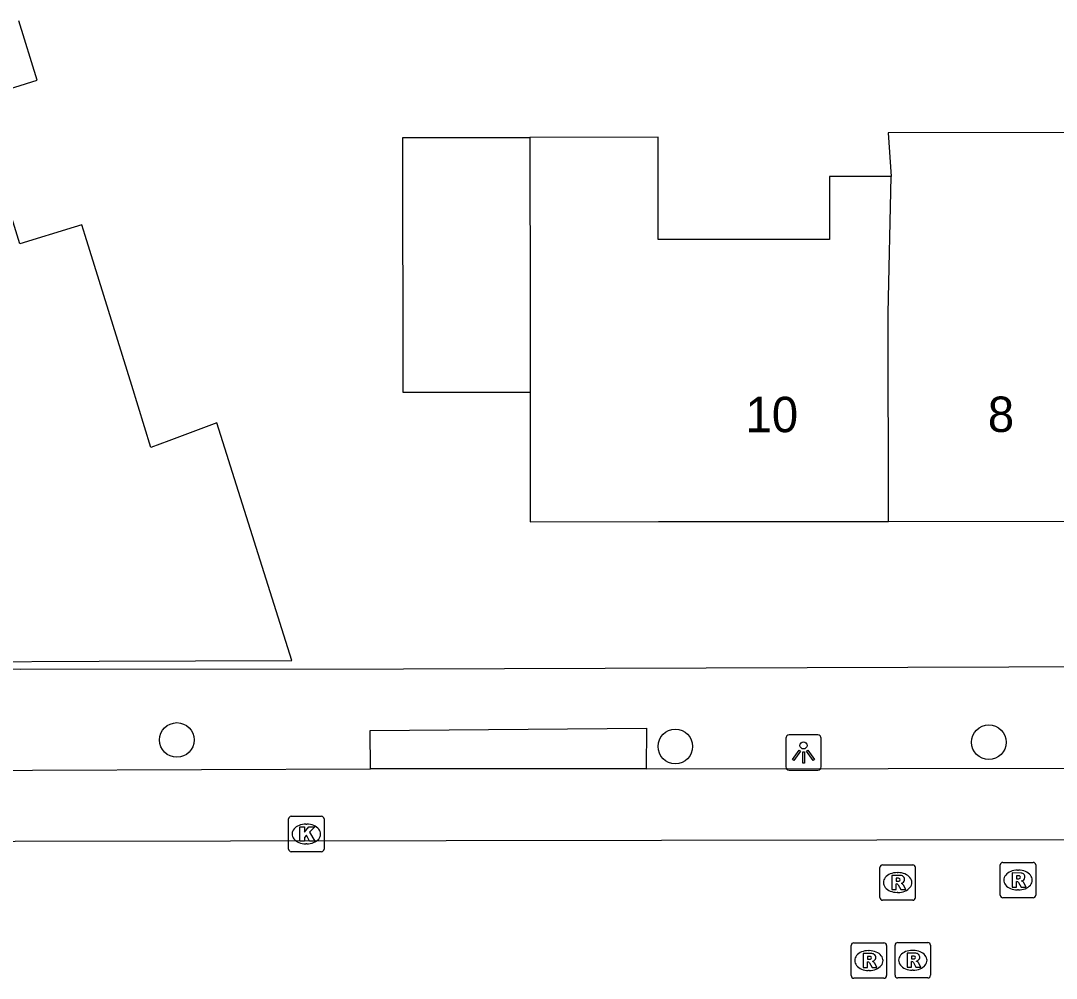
# Model space of a CAD drawing. Extents: x 160732 to 162105, y 387428 to 388479.
# Drawn here: x 161100.45 to 161129.69, y 388231.21 to 388258.26 of the extents above; entities that cross this region are included whole.
import ezdxf

# ---------------------------------------------------------------- set-up
doc = ezdxf.new("R2010")
doc.units = 0
for name, color, linetype in [('IMGEO_Boom', 7, 'Continuous'), ('IMGEO_Kolk', 7, 'Continuous'), ('IMGEO_Lichtpunt', 7, 'Continuous'), ('IMGEO_Muur', 7, 'Continuous'), ('IMGEO_Pand', 7, 'Continuous'), ('IMGEO_Pand_nummerreeks', 7, 'Continuous'), ('IMGEO_Rijbaan_lokaal_open', 7, 'Continuous'), ('IMGEO_Rioolput', 7, 'Continuous'), ('IMGEO_Voetpad_open', 7, 'Continuous')]:
    doc.layers.add(name, color=color, linetype=linetype)

msp = doc.modelspace()

# ---------------------------------------------------------------- linework, layer by layer
at = {"layer": 'IMGEO_Boom'}
for centre in [(161104.856, 388237.944), (161118.933, 388237.761), (161127.787, 388237.879)]:
    msp.add_circle(centre, 0.489, dxfattribs=at)
at = {"layer": 'IMGEO_Kolk'}
for p, q in [((161108.012, 388234.863), (161108.012, 388235.715)), ((161108.087, 388235.789), (161108.939, 388235.789)), ((161108.5, 388235.569), (161108.525, 388235.569)), ((161109.013, 388235.715), (161109.013, 388234.863)), ((161108.523, 388235.009), (161108.498, 388235.009)), ((161108.939, 388234.789), (161108.087, 388234.789))]:
    msp.add_line(p, q, dxfattribs=at)
for points in [[(161108.012, 388234.863), (161108.012, 388235.715)], [(161108.087, 388235.789), (161108.939, 388235.789)], [(161109.013, 388235.715), (161109.013, 388234.863)], [(161108.333, 388235.489), (161108.456, 388235.489), (161108.456, 388235.338), (161108.586, 388235.489), (161108.75, 388235.489), (161108.604, 388235.338), (161108.757, 388235.089), (161108.605, 388235.089), (161108.52, 388235.253), (161108.456, 388235.186), (161108.456, 388235.089), (161108.333, 388235.089), (161108.333, 388235.489)], [(161108.939, 388234.789), (161108.087, 388234.789)]]:
    msp.add_lwpolyline(points, dxfattribs=at)
for centre, start, end in [((161108.089, 388235.713), 91.552, 178.448), ((161108.089, 388235.713), 91.552, 178.448), ((161108.937, 388235.713), 1.552, 88.448), ((161108.937, 388235.713), 1.552, 88.448), ((161108.089, 388234.865), 181.552, 268.448), ((161108.089, 388234.865), 181.552, 268.448), ((161108.937, 388234.865), 271.552, 358.448), ((161108.937, 388234.865), 271.552, 358.448)]:
    msp.add_arc(centre, 0.0765, start, end, dxfattribs=at)
for centre, major_axis, ratio, start_param, end_param in [((161108.499, 388235.289), (-0.387, 0.002), 0.722429, 4.712389, 7.853982), ((161108.524, 388235.289), (-0.39, 0.002), 0.717154, 1.570796, 4.712389)]:
    msp.add_ellipse(centre, major_axis=major_axis, ratio=ratio, start_param=start_param, end_param=end_param, dxfattribs=at)
at = {"layer": 'IMGEO_Lichtpunt'}
for p, q in [((161122.054, 388237.991), (161122.054, 388237.184)), ((161122.054, 388237.991), (161122.054, 388237.184)), ((161122.956, 388238.086), (161122.148, 388238.086)), ((161122.956, 388238.086), (161122.148, 388238.086)), ((161123.05, 388237.184), (161123.05, 388237.991)), ((161123.05, 388237.184), (161123.05, 388237.991)), ((161122.148, 388237.09), (161122.956, 388237.09)), ((161122.148, 388237.09), (161122.956, 388237.09))]:
    msp.add_line(p, q, dxfattribs=at)
for points in [[(161122.428, 388237.655), (161122.467, 388237.627), (161122.279, 388237.365), (161122.241, 388237.392), (161122.428, 388237.655)], [(161122.53, 388237.607), (161122.577, 388237.607), (161122.577, 388237.285), (161122.53, 388237.285), (161122.53, 388237.607)], [(161122.64, 388237.627), (161122.678, 388237.654), (161122.865, 388237.392), (161122.826, 388237.364), (161122.64, 388237.627)]]:
    msp.add_lwpolyline(points, dxfattribs=at)
msp.add_circle((161122.553, 388237.789), 0.0994, dxfattribs=at)
for centre, start, end in [((161122.148, 388237.991), 90, 180), ((161122.148, 388237.991), 90, 180), ((161122.956, 388237.991), 0, 90), ((161122.956, 388237.991), 0, 90), ((161122.148, 388237.184), 180, 270), ((161122.148, 388237.184), 180, 270), ((161122.956, 388237.184), 270, 0), ((161122.956, 388237.184), 270, 360)]:
    msp.add_arc(centre, 0.0946, start, end, dxfattribs=at)
at = {"layer": 'IMGEO_Muur'}
msp.add_lwpolyline([(161111.252, 388239.945), (161100.452, 388239.931)], dxfattribs=at)
at = {"layer": 'IMGEO_Pand'}
for points in [[(161100.422, 388251.952), (161099.156, 388256.034), (161100.91, 388256.578), (161100.39, 388258.255)], [(161114.833, 388247.757), (161111.244, 388247.753), (161111.237, 388254.958), (161114.828, 388254.961)], [(161125.03, 388253.856), (161123.285, 388253.855), (161123.286, 388252.078), (161118.453, 388252.074), (161118.451, 388254.965), (161114.828, 388254.961)], [(161114.828, 388254.961), (161114.831, 388250), (161114.833, 388247.757)], [(161131.281, 388255.101), (161124.942, 388255.093), (161125.03, 388253.856)], [(161124.954, 388244.117), (161124.947, 388250), (161125.03, 388253.856)], [(161092.181, 388249.13), (161093.283, 388245.574), (161094.032, 388245.807), (161094.871, 388243.102), (161097.592, 388243.945), (161098.837, 388240.152), (161102.659, 388240.167), (161108.106, 388240.189), (161105.986, 388246.899), (161104.628, 388246.395), (161104.121, 388246.207), (161103.58, 388247.957), (161102.266, 388252.194), (161102.173, 388252.495), (161101.955, 388252.427), (161100.422, 388251.952)], [(161114.833, 388247.757), (161114.837, 388244.108), (161118.459, 388244.111), (161124.954, 388244.117)], [(161124.954, 388244.117), (161131.298, 388244.124)]]:
    msp.add_lwpolyline(points, dxfattribs=at)
at = {"layer": 'IMGEO_Rijbaan_lokaal_open'}
msp.add_lwpolyline([(161148.964, 388235.149), (161088.109, 388235.056)], dxfattribs=at)
at = {"layer": 'IMGEO_Rioolput'}
for p, q in [((161124.785, 388234.419), (161125.637, 388234.419)), ((161128.11, 388233.562), (161128.11, 388234.414)), ((161128.185, 388234.488), (161129.037, 388234.488)), ((161129.111, 388234.414), (161129.111, 388233.562)), ((161124.71, 388233.493), (161124.71, 388234.345)), ((161125.198, 388234.199), (161125.223, 388234.199)), ((161125.711, 388234.345), (161125.711, 388233.493)), ((161128.598, 388234.268), (161128.623, 388234.268)), ((161125.221, 388233.639), (161125.196, 388233.639)), ((161128.621, 388233.708), (161128.596, 388233.708)), ((161125.637, 388233.419), (161124.785, 388233.419)), ((161129.037, 388233.488), (161128.185, 388233.488)), ((161123.898, 388231.289), (161123.898, 388232.141)), ((161123.973, 388232.215), (161124.825, 388232.215)), ((161124.899, 388232.141), (161124.899, 388231.289)), ((161125.139, 388231.298), (161125.139, 388232.15)), ((161125.214, 388232.224), (161126.066, 388232.224)), ((161126.14, 388232.15), (161126.14, 388231.298)), ((161124.386, 388231.995), (161124.411, 388231.995)), ((161125.627, 388232.004), (161125.652, 388232.004)), ((161124.825, 388231.215), (161123.973, 388231.215)), ((161124.409, 388231.435), (161124.384, 388231.435)), ((161126.066, 388231.224), (161125.214, 388231.224)), ((161125.65, 388231.444), (161125.625, 388231.444))]:
    msp.add_line(p, q, dxfattribs=at)
for points in [[(161124.785, 388234.419), (161125.637, 388234.419)], [(161128.11, 388233.562), (161128.11, 388234.414)], [(161128.185, 388234.488), (161129.037, 388234.488)], [(161129.111, 388234.414), (161129.111, 388233.562)], [(161124.71, 388233.493), (161124.71, 388234.345)], [(161125.299, 388234.117), (161125.047, 388234.119), (161125.047, 388233.719)], [(161125.711, 388234.345), (161125.711, 388233.493)], [(161128.699, 388234.186), (161128.447, 388234.188), (161128.447, 388233.788)], [(161128.625, 388234.107), (161128.571, 388234.107), (161128.571, 388234.026)], [(161125.047, 388233.719), (161125.171, 388233.719), (161125.171, 388233.881), (161125.182, 388233.881)], [(161125.225, 388234.038), (161125.171, 388234.038), (161125.171, 388233.957)], [(161125.171, 388233.957), (161125.223, 388233.957)], [(161125.229, 388233.852), (161125.3, 388233.719), (161125.44, 388233.719), (161125.375, 388233.845)], [(161128.447, 388233.788), (161128.571, 388233.788), (161128.571, 388233.95), (161128.582, 388233.95)], [(161128.571, 388234.026), (161128.623, 388234.026)], [(161128.629, 388233.921), (161128.7, 388233.788), (161128.84, 388233.788), (161128.775, 388233.914)], [(161125.637, 388233.419), (161124.785, 388233.419)], [(161129.037, 388233.488), (161128.185, 388233.488)], [(161123.898, 388231.289), (161123.898, 388232.141)], [(161123.973, 388232.215), (161124.825, 388232.215)], [(161124.899, 388232.141), (161124.899, 388231.289)], [(161125.139, 388231.298), (161125.139, 388232.15)], [(161125.214, 388232.224), (161126.066, 388232.224)], [(161126.14, 388232.15), (161126.14, 388231.298)], [(161124.487, 388231.913), (161124.235, 388231.915), (161124.235, 388231.515)], [(161124.413, 388231.834), (161124.359, 388231.834), (161124.359, 388231.753)], [(161124.359, 388231.753), (161124.411, 388231.753)], [(161125.728, 388231.922), (161125.476, 388231.924), (161125.476, 388231.524)], [(161125.654, 388231.843), (161125.6, 388231.843), (161125.6, 388231.762)], [(161125.6, 388231.762), (161125.652, 388231.762)], [(161124.235, 388231.515), (161124.359, 388231.515), (161124.359, 388231.677), (161124.37, 388231.677)], [(161124.417, 388231.648), (161124.488, 388231.515), (161124.628, 388231.515), (161124.563, 388231.641)], [(161125.476, 388231.524), (161125.6, 388231.524), (161125.6, 388231.686), (161125.611, 388231.686)], [(161125.658, 388231.657), (161125.729, 388231.524), (161125.869, 388231.524), (161125.804, 388231.65)], [(161124.825, 388231.215), (161123.973, 388231.215)], [(161126.066, 388231.224), (161125.214, 388231.224)]]:
    msp.add_lwpolyline(points, dxfattribs=at)
for centre, radius, start, end in [((161124.787, 388234.343), 0.0765, 91.552, 178.448), ((161124.787, 388234.343), 0.0765, 91.552, 178.448), ((161125.635, 388234.343), 0.0765, 1.552, 88.448), ((161125.635, 388234.343), 0.0765, 1.552, 88.448), ((161128.187, 388234.412), 0.0765, 91.552, 178.448), ((161128.187, 388234.412), 0.0765, 91.552, 178.448), ((161129.035, 388234.412), 0.0765, 1.552, 88.448), ((161129.035, 388234.412), 0.0765, 1.552, 88.448), ((161125.298, 388234.007), 0.109, 350.3612, 89.416), ((161128.631, 388234.011), 0.0964, 77.0061, 93.1865), ((161128.645, 388234.068), 0.0378, 276.6634, 79.6772), ((161128.698, 388234.076), 0.109, 350.3612, 89.416), ((161125.181, 388233.828), 0.0533, 26.0293, 88.6989), ((161125.207, 388234.146), 0.19, 274.7715, 282.9687), ((161125.231, 388233.942), 0.0964, 77.0061, 93.1865), ((161125.245, 388233.999), 0.0378, 276.6634, 79.6772), ((161125.296, 388234.007), 0.112, 277.5842, 350.9817), ((161125.28, 388233.792), 0.108, 29.5134, 73.7905), ((161128.581, 388233.897), 0.0533, 26.0293, 88.6989), ((161128.607, 388234.215), 0.19, 274.7715, 282.9687), ((161128.696, 388234.076), 0.112, 277.5842, 350.9817), ((161128.68, 388233.861), 0.108, 29.5134, 73.7905), ((161128.187, 388233.564), 0.0765, 181.552, 268.448), ((161128.187, 388233.564), 0.0765, 181.552, 268.448), ((161129.035, 388233.564), 0.0765, 271.552, 358.448), ((161129.035, 388233.564), 0.0765, 271.552, 358.448), ((161124.787, 388233.495), 0.0765, 181.552, 268.448), ((161124.787, 388233.495), 0.0765, 181.552, 268.448), ((161125.635, 388233.495), 0.0765, 271.552, 358.448), ((161125.635, 388233.495), 0.0765, 271.552, 358.448), ((161123.975, 388232.139), 0.0765, 91.552, 178.448), ((161123.975, 388232.139), 0.0765, 91.552, 178.448), ((161124.823, 388232.139), 0.0765, 1.552, 88.448), ((161124.823, 388232.139), 0.0765, 1.552, 88.448), ((161125.216, 388232.148), 0.0765, 91.552, 178.448), ((161125.216, 388232.148), 0.0765, 91.552, 178.448), ((161126.064, 388232.148), 0.0765, 1.552, 88.448), ((161126.064, 388232.148), 0.0765, 1.552, 88.448), ((161124.395, 388231.942), 0.19, 274.7715, 282.9687), ((161124.419, 388231.738), 0.0964, 77.0061, 93.1865), ((161124.433, 388231.795), 0.0378, 276.6634, 79.6772), ((161124.486, 388231.803), 0.109, 350.3612, 89.416), ((161124.484, 388231.803), 0.112, 277.5842, 350.9817), ((161125.636, 388231.951), 0.19, 274.7715, 282.9687), ((161125.66, 388231.747), 0.0964, 77.0061, 93.1865), ((161125.674, 388231.804), 0.0378, 276.6634, 79.6772), ((161125.727, 388231.812), 0.109, 350.3612, 89.416), ((161125.725, 388231.812), 0.112, 277.5842, 350.9817), ((161124.369, 388231.624), 0.0533, 26.0293, 88.6989), ((161124.468, 388231.588), 0.108, 29.5134, 73.7905), ((161125.61, 388231.633), 0.0533, 26.0293, 88.6989), ((161125.709, 388231.597), 0.108, 29.5134, 73.7905), ((161123.975, 388231.291), 0.0765, 181.552, 268.448), ((161123.975, 388231.291), 0.0765, 181.552, 268.448), ((161124.823, 388231.291), 0.0765, 271.552, 358.448), ((161124.823, 388231.291), 0.0765, 271.552, 358.448), ((161125.216, 388231.3), 0.0765, 181.552, 268.448), ((161125.216, 388231.3), 0.0765, 181.552, 268.448), ((161126.064, 388231.3), 0.0765, 271.552, 358.448), ((161126.064, 388231.3), 0.0765, 271.552, 358.448)]:
    msp.add_arc(centre, radius, start, end, dxfattribs=at)
for centre, major_axis, ratio, start_param, end_param in [((161125.197, 388233.919), (-0.387, 0.002), 0.722429, 4.712389, 7.853982), ((161125.222, 388233.919), (-0.39, 0.002), 0.717154, 1.570796, 4.712389), ((161128.597, 388233.988), (-0.387, 0.002), 0.722429, 4.712389, 7.853982), ((161128.622, 388233.988), (-0.39, 0.002), 0.717154, 1.570796, 4.712389), ((161124.385, 388231.715), (-0.387, 0.002), 0.722429, 4.712389, 7.853982), ((161124.41, 388231.715), (-0.39, 0.002), 0.717154, 1.570796, 4.712389), ((161125.626, 388231.724), (-0.387, 0.002), 0.722429, 4.712389, 7.853982), ((161125.651, 388231.724), (-0.39, 0.002), 0.717154, 1.570796, 4.712389)]:
    msp.add_ellipse(centre, major_axis=major_axis, ratio=ratio, start_param=start_param, end_param=end_param, dxfattribs=at)
at = {"layer": 'IMGEO_Voetpad_open'}
for points in [[(161151.145, 388240.071), (161111.252, 388239.945), (161100.452, 388239.931), (161091.583, 388240.029)], [(161110.326, 388237.131), (161110.314, 388238.207), (161118.119, 388238.275), (161118.114, 388237.132)], [(161091.228, 388237.058), (161110.326, 388237.131)], [(161118.114, 388237.132), (161110.326, 388237.131)], [(161118.114, 388237.132), (161145.439, 388237.168)]]:
    msp.add_lwpolyline(points, dxfattribs=at)

# ---------------------------------------------------------------- texts
at = {"layer": 'IMGEO_Pand_nummerreeks'}
for s, p in [('10', (161120.915, 388246.634)), ('8', (161127.758, 388246.641))]:
    msp.add_text(s, height=1, rotation=0.0606, dxfattribs=at).set_placement(p)

doc.saveas('drawing.dxf')
